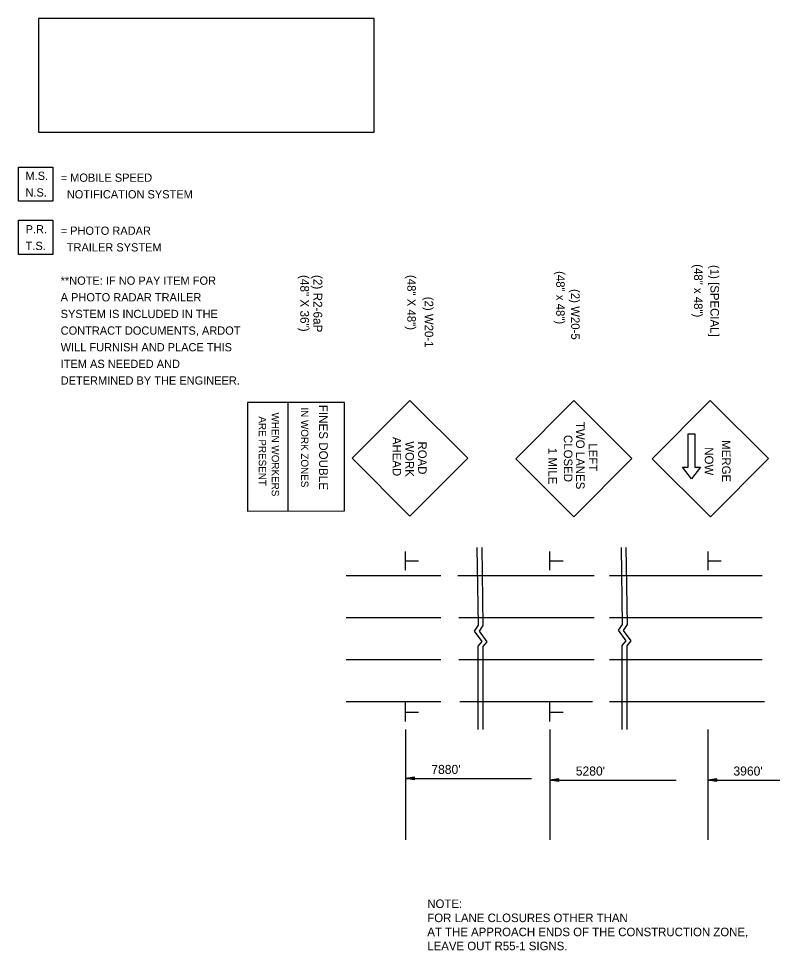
# Model space of a CAD drawing. Extents: x -100 to 745, y -1581 to -107.
# Drawn here: x -99.6 to -44.6, y -553.6 to -485.7 of the extents above; entities that cross this region are included whole.
import ezdxf

# ---------------------------------------------------------------- set-up
doc = ezdxf.new("R2010")
doc.units = 0
doc.layers.add('Default', color=7, linetype='Continuous')

msp = doc.modelspace()

# ---------------------------------------------------------------- linework, layer by layer
at = {"layer": 'Default'}
for p, q in [((-79.91, -521.597), (-79.916, -513.685)), ((-75.244, -517.748), (-71.037, -513.538)), ((-71.037, -513.538), (-66.826, -517.748)), ((-63.325, -517.783), (-59.095, -513.538)), ((-59.095, -513.538), (-54.853, -517.768)), ((-53.371, -517.783), (-49.141, -513.538)), ((-49.141, -513.538), (-44.899, -517.768)), ((-50.756, -518.397), (-50.756, -515.968)), ((-50.756, -515.968), (-50.26, -515.968)), ((-50.26, -515.968), (-50.26, -518.397)), ((-71.037, -521.959), (-75.244, -517.748)), ((-66.826, -517.748), (-71.037, -521.959)), ((-59.08, -522.013), (-63.325, -517.783)), ((-54.853, -517.768), (-59.08, -522.013)), ((-49.126, -522.013), (-53.371, -517.783)), ((-44.899, -517.768), (-49.126, -522.013)), ((-50.508, -519.255), (-51.168, -518.397)), ((-51.168, -518.397), (-50.756, -518.397)), ((-49.847, -518.397), (-50.508, -519.255)), ((-50.26, -518.397), (-49.847, -518.397)), ((-71.362, -525.914), (-71.362, -524.536)), ((-60.833, -525.914), (-60.833, -524.536)), ((-49.305, -525.914), (-49.305, -524.536)), ((-71.341, -525.229), (-70.401, -525.229)), ((-60.812, -525.229), (-59.872, -525.229)), ((-49.284, -525.229), (-48.344, -525.229)), ((-75.692, -526.292), (-68.785, -526.292)), ((-67.556, -526.292), (-57.608, -526.292)), ((-56.492, -526.292), (-45.364, -526.292)), ((-75.692, -529.354), (-68.785, -529.354)), ((-67.475, -529.354), (-57.608, -529.354)), ((-56.492, -529.354), (-45.364, -529.354)), ((-75.692, -532.416), (-68.785, -532.416)), ((-67.475, -532.416), (-57.608, -532.416)), ((-56.492, -532.416), (-45.364, -532.416)), ((-75.692, -535.479), (-68.785, -535.479)), ((-71.362, -536.936), (-71.362, -535.557)), ((-67.394, -535.479), (-57.727, -535.479)), ((-60.833, -536.936), (-60.833, -535.558)), ((-56.492, -535.479), (-45.202, -535.479)), ((-71.341, -536.25), (-70.4, -536.25)), ((-60.812, -536.25), (-59.872, -536.25)), ((-71.362, -537.506), (-71.362, -545.559)), ((-60.833, -537.506), (-60.833, -545.559)), ((-49.325, -537.506), (-49.325, -545.559)), ((-70.701, -540.982), (-71.362, -541.082)), ((-71.362, -541.082), (-62.168, -541.082)), ((-70.701, -541.181), (-71.362, -541.082)), ((-70.701, -540.999), (-71.251, -541.082)), ((-70.701, -541.164), (-71.251, -541.082)), ((-70.701, -541.016), (-71.138, -541.082)), ((-70.701, -541.147), (-71.138, -541.082)), ((-70.701, -541.032), (-71.028, -541.082)), ((-70.701, -541.131), (-71.028, -541.082)), ((-70.701, -541.049), (-70.916, -541.082)), ((-70.701, -541.114), (-70.916, -541.082)), ((-70.701, -541.066), (-70.805, -541.082)), ((-70.701, -541.097), (-70.805, -541.082)), ((-70.701, -541.181), (-70.701, -540.982)), ((-60.172, -541.1), (-60.833, -541.199)), ((-60.172, -541.116), (-60.722, -541.199)), ((-60.172, -541.133), (-60.609, -541.199)), ((-60.172, -541.298), (-60.172, -541.1)), ((-48.664, -541.1), (-49.325, -541.199)), ((-48.664, -541.116), (-49.214, -541.199)), ((-48.664, -541.133), (-49.101, -541.199)), ((-48.664, -541.298), (-48.664, -541.1)), ((-60.833, -541.199), (-51.639, -541.199)), ((-60.172, -541.298), (-60.833, -541.199)), ((-60.172, -541.282), (-60.722, -541.199)), ((-60.172, -541.265), (-60.609, -541.199)), ((-60.172, -541.15), (-60.499, -541.199)), ((-60.172, -541.248), (-60.499, -541.199)), ((-60.172, -541.167), (-60.387, -541.199)), ((-60.172, -541.231), (-60.387, -541.199)), ((-60.172, -541.183), (-60.276, -541.199)), ((-60.172, -541.214), (-60.276, -541.199)), ((-49.325, -541.199), (-40.131, -541.199)), ((-48.664, -541.298), (-49.325, -541.199)), ((-48.664, -541.282), (-49.214, -541.199)), ((-48.664, -541.265), (-49.101, -541.199)), ((-48.664, -541.15), (-48.991, -541.199)), ((-48.664, -541.248), (-48.991, -541.199)), ((-48.664, -541.167), (-48.879, -541.199)), ((-48.664, -541.231), (-48.879, -541.199)), ((-48.664, -541.183), (-48.768, -541.199)), ((-48.664, -541.214), (-48.768, -541.199))]:
    msp.add_line(p, q, dxfattribs=at)
for points in [[(-98.121, -493.976), (-73.632, -493.976), (-73.632, -485.713), (-98.121, -485.713)], [(-99.558, -499.026), (-99.558, -496.526), (-97.058, -496.526), (-97.058, -499.026)], [(-99.558, -502.891), (-99.558, -500.391), (-97.058, -500.391), (-97.058, -502.891)], [(-75.814, -513.682), (-82.885, -513.688), (-82.878, -521.599), (-75.807, -521.593)]]:
    msp.add_lwpolyline(points, close=True, dxfattribs=at)
for points in [[(-66.149, -524.265), (-66.063, -529.914), (-66.349, -530.339), (-65.792, -531.102), (-66.085, -531.454), (-66.086, -537.506)], [(-65.797, -524.265), (-65.711, -529.928), (-65.997, -530.354), (-65.44, -531.116), (-65.733, -531.469), (-65.734, -537.506)], [(-55.647, -524.265), (-55.562, -529.855), (-55.848, -530.28), (-55.29, -531.043), (-55.584, -531.395), (-55.585, -537.506)], [(-55.295, -524.265), (-55.21, -529.87), (-55.496, -530.295), (-54.938, -531.058), (-55.232, -531.41), (-55.233, -537.506)]]:
    msp.add_lwpolyline(points, dxfattribs=at)

# ---------------------------------------------------------------- texts
for s, height, p in [('M.S.', 0.6, (-99.06, -497.466)), ('= MOBILE SPEED', 0.6, (-96.493, -497.602)), ('N.S.', 0.6, (-99.06, -498.679)), ('  NOTIFICATION SYSTEM', 0.6, (-96.493, -498.815)), ('P.R.', 0.6, (-99.049, -501.361)), ('= PHOTO RADAR', 0.6, (-96.493, -501.467)), ('T.S.', 0.6, (-99.049, -502.574)), ('  TRAILER SYSTEM', 0.6, (-96.493, -502.68)), ('**NOTE: IF NO PAY ITEM FOR', 0.6, (-96.493, -505.106)), ('A PHOTO RADAR TRAILER', 0.6, (-96.493, -506.319)), ('SYSTEM IS INCLUDED IN THE', 0.6, (-96.493, -507.532)), ('CONTRACT DOCUMENTS, ARDOT', 0.6, (-96.493, -508.745)), ('WILL FURNISH AND PLACE THIS', 0.6, (-96.493, -509.958)), ('ITEM AS NEEDED AND', 0.6, (-96.493, -511.171)), ('DETERMINED BY THE ENGINEER.', 0.6, (-96.493, -512.384)), ("7880'", 0.6606, (-69.478, -540.756)), ("5280'", 0.6606, (-58.949, -540.873)), ("3960'", 0.6606, (-47.457, -540.873)), ('NOTE:', 0.6222, (-69.77, -550.527)), ('FOR LANE CLOSURES OTHER THAN ', 0.6222, (-69.77, -551.552)), ('AT THE APPROACH ENDS OF THE CONSTRUCTION ZONE,', 0.6222, (-69.77, -552.577)), ('LEAVE OUT R55-1 SIGNS.', 0.6222, (-69.77, -553.602))]:
    msp.add_text(s, height=height, dxfattribs=at).set_placement(p)
for s, height, rotation, p in [('(48" x 48")', 0.6222, 270, (-50.327, -503.606)), ('(1) [SPECIAL]', 0.6222, 270, (-49.13, -503.665)), ('(48" X 36")', 0.64008, 270.05011, (-79.031, -504.394)), ('(2) R2-6aP', 0.6401, 270.05011, (-78.071, -504.393)), ('(48" X 48")', 0.6222, 270, (-71.229, -504.393)), ('(48" x 48")', 0.6222, 270, (-60.375, -504.109)), ('(2) W20-5', 0.6222, 270, (-59.285, -505.417)), ('(2) W20-1', 0.6222, 270, (-69.956, -505.98)), ('FINES DOUBLE', 0.63252, 270.05011, (-77.658, -513.857)), ('WHEN WORKERS', 0.53714, 270.05011, (-81.115, -514.418)), ('IN WORK ZONES', 0.53703, 270.05011, (-78.976, -514.045)), ('ARE PRESENT', 0.53714, 270.05011, (-82.056, -514.699)), ('TWO LANES', 0.6243, 270.10045, (-58.936, -515.101)), (' AHEAD', 0.6203, 270.00057, (-72.298, -515.966)), ('WORK', 0.6201, 270.00004, (-71.367, -516.519)), ('ROAD', 0.6203, 270.00045, (-70.437, -516.532)), ('CLOSED', 0.6242, 270.10034, (-59.819, -516.053)), ('MERGE', 0.6243, 270.10045, (-48.296, -516.433)), ('1 MILE', 0.6283, 270.00057, (-60.948, -516.988)), ('LEFT', 0.6243, 270.10045, (-57.997, -516.656)), ('NOW', 0.6242, 270.10034, (-49.545, -516.949))]:
    msp.add_text(s, height=height, rotation=rotation, dxfattribs=at).set_placement(p)

doc.saveas('drawing.dxf')
